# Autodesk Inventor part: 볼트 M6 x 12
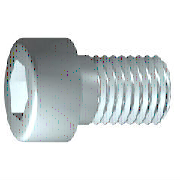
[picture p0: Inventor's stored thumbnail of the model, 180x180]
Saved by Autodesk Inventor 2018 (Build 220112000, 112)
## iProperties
IsCustomPart: 1
Created: 2012-02
Part Number: 볼트 M6 x 12
Material: 강철, 연강
Description: 원통형 머리 캡 나사
Document SubType Name: Modeling
Standard: JIS B 1176
Designer: mdu-01
Standards Organization: JIS
Language: ko-KR
Size Designation: M6 x 12
Categories: <MemberInstance><Categories><Category DisplayName="조임쇠" InternalName="e4da775c-781d-43d5-af7c-5136215cf5a6" Mnemonic="FSTN"><Category DisplayName="볼트" InternalN
Density: 1 g/cm^3
Appearance: 강철
Author: mdu-01
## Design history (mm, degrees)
sketch "스케치1"
  geometry: L1 (-1.333, 0)-(12, 0); L2 (12, 0)-(12, 3); L3 (12, 3)-(2.5, 3); L4 (2.5, 3)-(1.886, 3); L5 (1.886, 3)-(0, 3); L6 (0, 3)-(0, 5); L7 (0, 5)-(-6, 5); L8 (-6, 5)-(-6, 2.887); L9 (-6, 2.887)-(-3, 2.887); L10 (-3, 2.887)-(-1.333, 0); L11 (-9.6, 0)-(15.6, 0) reference; L12 (0, -1)-(0, 6) reference; L13 (2.5, 3)-(0, 3)
  constraints: 22 end point, 6 parallel, 2 collinear, 2 perpendicular, 1 horizontal, 1 point on line
  dimensions: "d1" = 9.5 distance from line of L3.end L2 (= GEL); "d2" = 0.61355 distance of L4.end L3.end (computed from GAL); "d3" = 6 distance between parallel lines of L8 L6 (= KOH); "d4" = 3 distance of L8.end L9.end (= INTI); "d5" = 60 deg angle of L10 L1; "d6" = 6 diameter of L3 L1 (= GD); "d7" = 6 diameter of L5 L1 (= BDM); "d8" = 5.7735 diameter of L9 L1 (= 1.1547 x SW); "d9" = 10 diameter of L7 L1 (= KOD); "d26" = 12 distance between parallel lines of L12 L2 (= NLG)
revolve "본체" sketch "스케치1" stored, may be unused: angle "d10" = 90 deg
sketch "스케치2"
  geometry: L1 (0, -7)-(0, 7) reference; L2 (-7, 0)-(7, 0) reference; L3 (2.887, 0)-(1.443, -2.5); L4 (1.443, -2.5)-(-1.443, -2.5); L5 (-1.443, -2.5)-(-2.887, 0); L6 (-2.887, 0)-(-1.443, 2.5); L7 (-1.443, 2.5)-(1.443, 2.5); L8 (1.443, 2.5)-(2.887, 0); 2 further points
  constraints: 12 end point, 1 coincident, 1 horizontal alignment, 1 point on line, 12 other
extrude "슬롯" join sketch "스케치2" stored distance "d11" = 10; taper "d12" = 0 deg
workplane "Work Plane1"
fillet "Fillet2" dims "d30" = 0.1 (= R)
body "Solid1"
fillet "모깎기1" dims "d17" = 0.6 (= RR)
feature "스레드" dims "d13" = 9.5 (= GEL), "d14" = 0
chamfer "모따기1" distance "d15" = 0.61345 (= -0.5 x SPD + 0.5 x GD); stored, may be unused: second distance "d16" = 0.61345 (= GUL), angle "d27" = 45 deg
other parameters: "GD" = 6 (= NND) [user parameter; used in 2 equation terms], "NLG" = 12 [user parameter; used in 1 equation term], "GEL" = 9.5 [user parameter; used in 2 equation terms], "KOD" = 10 [user parameter; used in 1 equation term], "KOH" = 6 [user parameter; used in 1 equation term], "INTI" = 3 [user parameter; used in 1 equation term], "GAL" = 0.61345 (= 0.61345 x PTC) [user parameter; used in 1 equation term], "GUL" = 0.61345 (= 0.61345 x PTC) [user parameter; used in 1 equation term], "BDM" = 6 (= NND) [user parameter; used in 1 equation term], "SW" = 5 [user parameter; used in 2 equation terms], "RR" = 0.6 [user parameter; used in 1 equation term], "SPD" = 4.7731 (= NND - 1.2269 x PTC) [user parameter; used in 1 equation term], "d19" = 0, "d28" = 0, "d29" = 0, "R" = 0.1 [user parameter; used in 1 equation term], "PHH" = 0.25 [user parameter], "GD1" = 4.7731 (= THREADDIA - 1.2269 x PTC) [user parameter], "THREADDIA" = 6 [user parameter; used in 1 equation term], "FAWI" = 45 deg [user parameter], "PTC" = 1 [user parameter; used in 5 equation terms], "NND" = 6 [user parameter; used in 3 equation terms], "TOA" = 30 deg [user parameter], "E0" = 5.775 (= 1.155 x SW) [user parameter]
